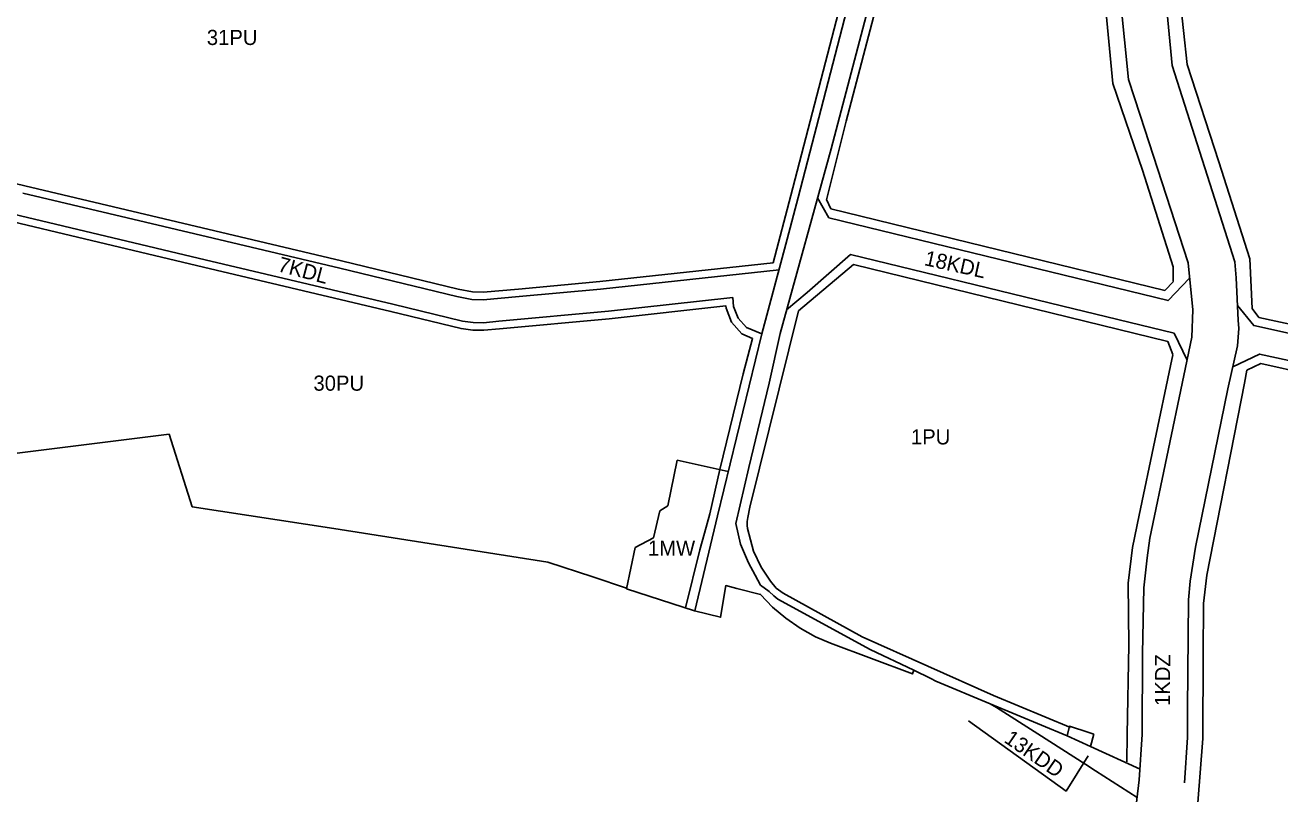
# Model space of a CAD drawing. Extents: x 7428203 to 7432868, y 5542672 to 5545406.
# Drawn here: x 7430591 to 7431420, y 5543351 to 5543859 of the extents above; entities that cross this region are included whole.
import ezdxf

# ---------------------------------------------------------------- set-up
doc = ezdxf.new("R2010")
doc.units = 0
for name, color, linetype in [('linie_rozgraniczajace', 7, 'Continuous'), ('linie_zabudowy_nieprzekraczalne', 7, 'Continuous'), ('oznaczenia_przeznaczen', 7, 'Continuous')]:
    doc.layers.add(name, color=color, linetype=linetype)

msp = doc.modelspace()

# ---------------------------------------------------------------- linework, layer by layer
at = {"layer": 'linie_rozgraniczajace'}
for p, q in [((7431165.55, 5543937.59), (7431123.36, 5543776.97)), ((7431123.36, 5543776.97), (7431089.64, 5543655.03)), ((7430715.18, 5543717.91), (7430589.68, 5543747.58)), ((7431121.78, 5543731.38), (7431114.43, 5543744.68)), ((7430710.02, 5543703.71), (7430583.41, 5543733.76)), ((7430798.9, 5543698.1), (7430715.18, 5543717.91)), ((7431094.31, 5543717.17), (7431077.61, 5543654.85)), ((7430833.88, 5543674.42), (7430710.02, 5543703.71)), ((7431107.52, 5543682.17), (7431136.12, 5543707.23)), ((7431136.12, 5543707.23), (7431275.47, 5543673.31)), ((7430876.12, 5543679.31), (7430798.9, 5543698.1)), ((7431088.94, 5543697.11), (7430971.13, 5543684.26)), ((7430886.02, 5543677.47), (7430876.12, 5543679.31)), ((7430893.64, 5543677.18), (7430886.02, 5543677.47)), ((7430917.35, 5543679.36), (7430893.64, 5543677.18)), ((7430971.13, 5543684.26), (7430917.35, 5543679.36)), ((7431058.52, 5543678.7), (7430976.29, 5543669.73)), ((7431058.91, 5543672.88), (7431058.52, 5543678.7)), ((7431093.95, 5543670.63), (7431107.52, 5543682.17)), ((7430879.84, 5543663.13), (7430833.88, 5543674.42)), ((7430976.29, 5543669.73), (7430903.91, 5543663.06)), ((7431061.86, 5543665.19), (7431058.91, 5543672.88)), ((7430887.02, 5543662.23), (7430879.84, 5543663.13)), ((7430893.75, 5543662.12), (7430887.02, 5543662.23)), ((7430903.91, 5543663.06), (7430893.75, 5543662.12)), ((7431067.42, 5543658.94), (7431061.86, 5543665.19)), ((7431077.61, 5543654.85), (7431048.24, 5543534.65)), ((7431077.61, 5543654.85), (7431067.42, 5543658.94)), ((7431349.97, 5543655.13), (7431358.39, 5543637.39)), ((7430580.6, 5543575.31), (7430686.19, 5543588.57)), ((7430686.19, 5543588.57), (7430701.37, 5543540.45)), ((7431015.5, 5543541.29), (7431021.74, 5543571.34)), ((7431021.74, 5543571.34), (7431055.36, 5543563.79)), ((7430701.37, 5543540.45), (7430795.01, 5543526.17)), ((7431006.07, 5543520.07), (7431010.15, 5543537.97)), ((7431010.15, 5543537.97), (7431015.5, 5543541.29)), ((7431048.24, 5543534.65), (7431033.4, 5543471.78)), ((7430795.01, 5543526.17), (7430936.27, 5543503.99)), ((7430993.86, 5543513.61), (7431006.07, 5543520.07)), ((7431332, 5543506.96), (7431333.87, 5543519.93)), ((7430988.17, 5543486.46), (7430993.86, 5543513.61)), ((7430936.27, 5543503.99), (7430965.97, 5543494.23)), ((7431068.81, 5543503.5), (7431073.16, 5543495.48)), ((7431329.75, 5543486.99), (7431332, 5543506.96)), ((7431073.16, 5543495.48), (7431076.77, 5543488.83)), ((7430965.97, 5543494.23), (7430988.24, 5543486.82)), ((7431076.77, 5543488.83), (7431082.34, 5543484.54)), ((7431329.06, 5543443.63), (7431329.75, 5543486.99)), ((7430988.17, 5543486.46), (7431033.18, 5543471.84)), ((7431082.34, 5543484.54), (7431085.5, 5543481.75)), ((7431085.5, 5543481.75), (7431088.17, 5543479.66)), ((7431088.17, 5543479.66), (7431149.24, 5543446.28)), ((7431149.24, 5543446.28), (7431178, 5543432.69)), ((7431328.85, 5543390.18), (7431329.06, 5543443.63)), ((7431178, 5543432.69), (7431178.03, 5543432.68)), ((7431178.03, 5543432.68), (7431189.14, 5543427.07)), ((7431189.14, 5543427.07), (7431192.47, 5543425.38)), ((7431192.47, 5543425.38), (7431228.37, 5543410.35)), ((7431232.58, 5543407.99), (7431228.37, 5543410.35)), ((7431228.37, 5543410.35), (7431279.17, 5543389.27)), ((7431358.76, 5543407.05), (7431358.78, 5543388.18)), ((7431296.83, 5543390.4), (7431294.71, 5543382.36)), ((7431356.78, 5543358.24), (7431358.78, 5543388.18)), ((7431291.6, 5543370.34), (7431298.04, 5543366.23)), ((7431325.38, 5543348.66), (7431298.04, 5543366.23))]:
    msp.add_line(p, q, dxfattribs=at)
for points in [[(7431336.87, 5543994.72), (7431337.06, 5543957.82), (7431342.05, 5543907.45), (7431346.33, 5543901.64), (7431344.13, 5543878.23), (7431348.52, 5543831.97), (7431390, 5543702.36), (7431390.73, 5543691.85), (7431392.19, 5543663.75), (7431392.48, 5543658.26), (7431391.71, 5543646.79), (7431385.31, 5543618.42), (7431364, 5543513.86)], [(7431094.31, 5543717.17), (7431101.48, 5543744.76), (7431145.8, 5543915.56), (7431159, 5543967.17), (7431163.66, 5543988.83)], [(7431333.87, 5543519.93), (7431356.3, 5543627.18), (7431361.52, 5543652.65), (7431362.19, 5543670.59), (7431359.03, 5543701.57), (7431327.35, 5543799.07), (7431319.67, 5543822.68), (7431309.1, 5543927.71)], [(7431121.78, 5543731.38), (7431345.9, 5543676.71), (7431360.06, 5543691.52)], [(7431275.47, 5543673.31), (7431349.97, 5543655.13)], [(7431649.61, 5543661.01), (7431590.67, 5543649.59), (7431556.92, 5543645.08), (7431530.11, 5543643.19), (7431505.43, 5543642.9), (7431491.22, 5543643.07), (7431484.24, 5543643.38), (7431477.62, 5543644.1), (7431468.99, 5543645.49), (7431402.48, 5543660.21), (7431391.69, 5543673.42)], [(7431068.81, 5543503.5), (7431063.6, 5543515.96), (7431060.51, 5543529.56), (7431068.98, 5543566.54), (7431082.49, 5543622.16), (7431089.64, 5543655.03)], [(7431653.54, 5543644.48), (7431593.24, 5543632.39), (7431558.54, 5543627.75), (7431530.83, 5543625.8), (7431505.53, 5543625.5), (7431490.89, 5543625.68), (7431483.19, 5543626.02), (7431475.72, 5543626.83), (7431466.29, 5543628.35), (7431406.24, 5543641.45), (7431388.58, 5543632.9)], [(7431364, 5543513.86), (7431360.54, 5543491.54), (7431359.35, 5543479.02), (7431358.76, 5543407.05)], [(7431033.18, 5543471.84), (7431050.36, 5543467.64), (7431053.78, 5543488.54), (7431061.07, 5543486.69)], [(7431061.07, 5543486.69), (7431076.77, 5543482.72), (7431084.69, 5543474.3), (7431093.41, 5543466.95), (7431102.96, 5543460.38), (7431112.94, 5543454.78), (7431122.89, 5543450.59), (7431177.06, 5543430.2), (7431178, 5543432.69)], [(7431232.58, 5543407.99), (7431259.81, 5543390.73), (7431291.6, 5543370.34)], [(7431296.83, 5543390.4), (7431293.43, 5543391.53), (7431280.69, 5543395.65), (7431279.17, 5543389.27), (7431294.67, 5543382.38)], [(7431324.03, 5543337.93), (7431326.85, 5543360.24), (7431328.85, 5543390.18)], [(7431327.32, 5543367.4), (7431294.67, 5543382.38)]]:
    msp.add_lwpolyline(points, dxfattribs=at)
at = {"layer": 'linie_zabudowy_nieprzekraczalne'}
for p, q in [((7431161.79, 5543903.59), (7431133.34, 5543795.27)), ((7431133.34, 5543795.27), (7431120.27, 5543743.3)), ((7431120.26, 5543743.37), (7431123.21, 5543737.21)), ((7431101.77, 5543669.93), (7431069.64, 5543540.37)), ((7431407.18, 5543635.16), (7431397.88, 5543630.74)), ((7431447.06, 5543626.25), (7431407.18, 5543635.16)), ((7431069.64, 5543540.37), (7431068.32, 5543533.48)), ((7431068, 5543530.75), (7431067.87, 5543528.16)), ((7431067.87, 5543528.16), (7431068.02, 5543526.15)), ((7431068.32, 5543533.48), (7431068, 5543530.75)), ((7431068.02, 5543526.15), (7431072.2, 5543511.28)), ((7431072.2, 5543511.28), (7431077.25, 5543500.75)), ((7431077.25, 5543500.75), (7431083.31, 5543491.36)), ((7431083.31, 5543491.36), (7431087.01, 5543486.91)), ((7431087.01, 5543486.91), (7431091.6, 5543483.47)), ((7431091.6, 5543483.47), (7431143.91, 5543454.73)), ((7431143.91, 5543454.73), (7431230.67, 5543415.89)), ((7431230.67, 5543415.89), (7431281.47, 5543394.81))]:
    msp.add_line(p, q, dxfattribs=at)
for points in [[(7431349.2, 5543689.58), (7431349.15, 5543699.08), (7431349.15, 5543699.08), (7431328.95, 5543762.85), (7431309.36, 5543820.12), (7431299.15, 5543926.71), (7431295.65, 5543954.49), (7431295.22, 5543975.54), (7431296.68, 5544010.53), (7431304.12, 5544109.78), (7431310.11, 5544189.63), (7431300.19, 5544190.78)], [(7430364.22, 5543909.88), (7430366.87, 5543843.51), (7430367.55, 5543835.53), (7430369.32, 5543828.42), (7430372.62, 5543820.8), (7430376.79, 5543814.37), (7430380.91, 5543809.7), (7430385.37, 5543805.8), (7430393.16, 5543800.91), (7430401.08, 5543798.21), (7430590.92, 5543752.42), (7430800.06, 5543702.97), (7430877.17, 5543684.2), (7430886.57, 5543682.45), (7430893.51, 5543682.18), (7430916.89, 5543684.34), (7430970.59, 5543689.23), (7431085, 5543701.71), (7431096.64, 5543746.01), (7431141.07, 5543916.56)], [(7431356.33, 5543901.17), (7431353.52, 5543877.68), (7431358.38, 5543832.7), (7431379.41, 5543768.24), (7431399.89, 5543704.26), (7431401.46, 5543671.4)], [(7431065.36, 5543628.41), (7431071.52, 5543651.7), (7431064.4, 5543654.82), (7431057.52, 5543662.55), (7431053.97, 5543671.8), (7431053.88, 5543673.17), (7430976.83, 5543664.76), (7430904.37, 5543658.08), (7430893.94, 5543657.12), (7430886.66, 5543657.24), (7430878.99, 5543658.2), (7430832.69, 5543669.56), (7430708.87, 5543698.85), (7430499.81, 5543748.5), (7430424.28, 5543766.84), (7430394.08, 5543774.18), (7430383.18, 5543777.9), (7430377.88, 5543780.73), (7430363.42, 5543791.79), (7430360.03, 5543794.93), (7430352.73, 5543805.17)], [(7431123.21, 5543737.21), (7431233.95, 5543710.19), (7431343.72, 5543683.42), (7431349.51, 5543689.34)], [(7431348.94, 5543641.03), (7431345.78, 5543649.62), (7431138.11, 5543700.58), (7431101.77, 5543669.93)], [(7431401.46, 5543671.4), (7431405.81, 5543665.62), (7431474.26, 5543650.72), (7431488.04, 5543649.22), (7431505.94, 5543648.91), (7431543.09, 5543650.12), (7431556.31, 5543651.05), (7431591.53, 5543655.87), (7431645.69, 5543666.48), (7431650.7, 5543673.62)], [(7431326.82, 5543535.01), (7431347.4, 5543633.65), (7431348.92, 5543640.96)], [(7431027.16, 5543473.79), (7431036.56, 5543512.04), (7431039.75, 5543523.06), (7431043.31, 5543535.8), (7431049.83, 5543565.15), (7431065.36, 5543628.41)], [(7431397.88, 5543630.74), (7431396.26, 5543622.17), (7431371.53, 5543495.49)], [(7431322.26, 5543513.71), (7431326.84, 5543534.92)], [(7431318.53, 5543372.2), (7431318.85, 5543390.22), (7431319.91, 5543449.08), (7431319.53, 5543490.11), (7431322.26, 5543513.71)], [(7431371.53, 5543495.49), (7431369.17, 5543476.66), (7431369.05, 5543442.73), (7431368.76, 5543387.51), (7431365.58, 5543344.99)]]:
    msp.add_lwpolyline(points, dxfattribs=at)
at = {"layer": 'oznaczenia_przeznaczen'}
msp.add_lwpolyline([(7431214.03, 5543399.28), (7431278.49, 5543352.81), (7431293.17, 5543376.18)], dxfattribs=at)

# ---------------------------------------------------------------- texts
for s, p in [('31PU', (7430711.0928, 5543845.49)), ('30PU', (7430781.4928, 5543617.2)), ('1PU', (7431176.0459, 5543581.73)), ('1MW', (7431002.3769, 5543508.25))]:
    msp.add_text(s, height=10, dxfattribs=at).set_placement(p)
for s, rotation, p in [('7KDL', 345.0952611, (7430757.3702, 5543696.2127)), ('18KDL', 347.5062908, (7431184.3687, 5543700.1782)), ('1KDZ', 89.7665967, (7431347.1353, 5543409.0206)), ('13KDD', 325.4615262, (7431236.9069, 5543385.5545))]:
    msp.add_text(s, height=10, rotation=rotation, dxfattribs=at).set_placement(p)

doc.saveas('drawing.dxf')
